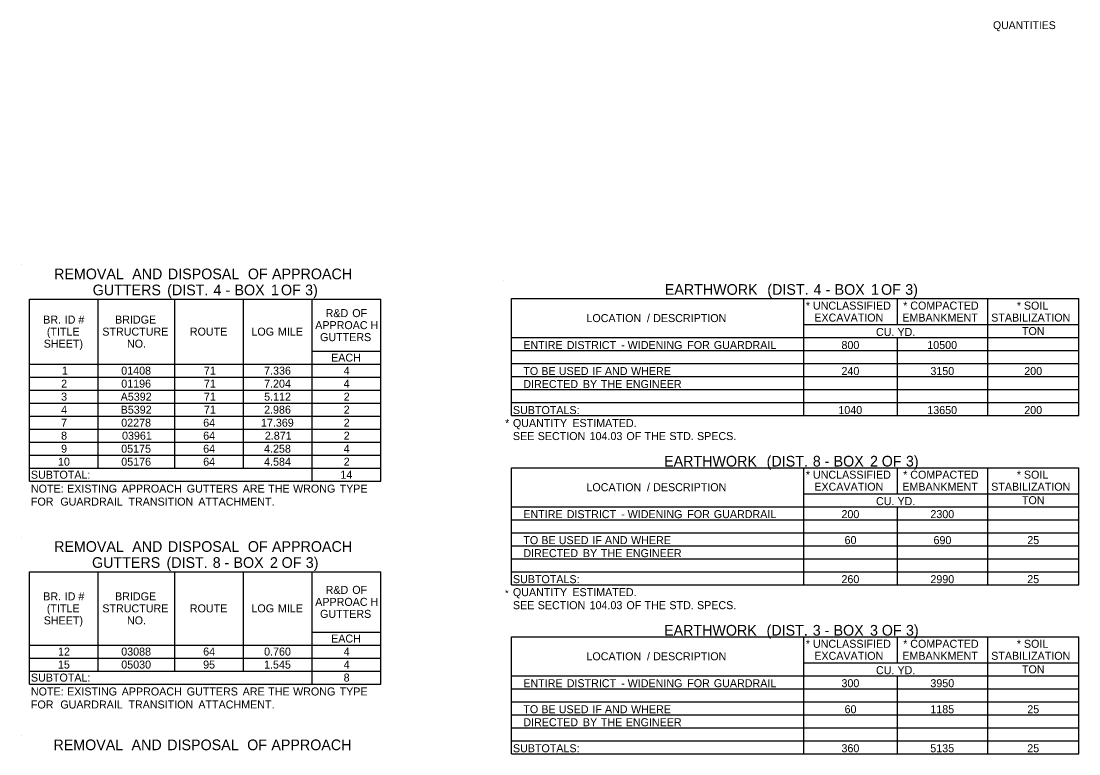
# Model space of a CAD drawing. Extents: x 540541 to 1930787, y -1948574 to 596640.
# Drawn here: x 544935 to 545728, y -1948135 to -1947586 of the extents above; entities that cross this region are included whole.
import ezdxf

# ---------------------------------------------------------------- set-up
doc = ezdxf.new("R2010")
doc.units = 0
for name, color, linetype in [('Default', 7, 'Continuous'), ('R_Border', 7, 'Continuous'), ('R_Border Prem', 7, 'Continuous')]:
    doc.layers.add(name, color=color, linetype=linetype)

msp = doc.modelspace()

# ---------------------------------------------------------------- linework, layer by layer
at = {"layer": 'Default'}
for p, q in [((544941.18, -1947794.32), (545204.43, -1947794.32)), ((544941.18, -1947930.82), (544941.18, -1947794.32)), ((544941.18, -1947930.82), (544941.18, -1947794.32)), ((544992.66, -1947921.07), (544992.66, -1947794.32)), ((545049.99, -1947921.07), (545049.99, -1947794.32)), ((545101.47, -1947921.07), (545101.47, -1947794.32)), ((545152.95, -1947930.82), (545152.95, -1947794.32)), ((545204.43, -1947930.82), (545204.43, -1947794.32)), ((545302.43, -1947793.93), (545727.53, -1947793.93)), ((545302.43, -1947871.93), (545302.43, -1947793.93)), ((545302.43, -1947881.68), (545302.43, -1947793.93)), ((545521.31, -1947881.68), (545521.31, -1947793.93)), ((545591.51, -1947813.43), (545591.51, -1947793.93)), ((545659.28, -1947881.68), (545659.28, -1947793.93)), ((545727.53, -1947881.68), (545727.53, -1947793.93)), ((545521.31, -1947813.43), (545727.53, -1947813.43)), ((545302.43, -1947823.18), (545727.53, -1947823.18)), ((545591.51, -1947881.68), (545591.51, -1947823.18)), ((545152.95, -1947833.32), (545204.43, -1947833.32)), ((545152.95, -1947833.32), (545204.43, -1947833.32)), ((545302.43, -1947832.93), (545727.53, -1947832.93)), ((544941.18, -1947843.07), (545204.43, -1947843.07)), ((545049.99, -1947921.07), (545049.99, -1947843.07)), ((545101.47, -1947921.07), (545101.47, -1947843.07)), ((545302.43, -1947842.68), (545727.53, -1947842.68)), ((544941.18, -1947852.82), (545204.43, -1947852.82)), ((545302.43, -1947852.43), (545727.53, -1947852.43)), ((544941.18, -1947862.57), (545204.43, -1947862.57)), ((544992.66, -1947921.07), (544992.66, -1947862.57)), ((545152.95, -1947930.82), (545152.95, -1947862.57)), ((545302.43, -1947862.18), (545727.53, -1947862.18)), ((544941.18, -1947872.32), (545204.43, -1947872.32)), ((545302.43, -1947871.93), (545727.53, -1947871.93)), ((544941.18, -1947882.07), (545204.43, -1947882.07)), ((545302.43, -1947881.68), (545727.53, -1947881.68)), ((544941.18, -1947891.82), (545204.43, -1947891.82)), ((544941.18, -1947901.57), (545204.43, -1947901.57)), ((544941.18, -1947911.32), (545204.43, -1947911.32)), ((544941.18, -1947921.07), (545204.43, -1947921.07)), ((544941.18, -1947921.07), (545204.43, -1947921.07)), ((545302.43, -1947920.68), (545727.53, -1947920.68)), ((545302.43, -1947998.68), (545302.43, -1947920.68)), ((545302.43, -1948008.43), (545302.43, -1947920.68)), ((545521.31, -1948008.43), (545521.31, -1947920.68)), ((545591.51, -1947940.18), (545591.51, -1947920.68)), ((545659.28, -1948008.43), (545659.28, -1947920.68)), ((545727.53, -1948008.43), (545727.53, -1947920.68)), ((544941.18, -1947930.82), (545204.43, -1947930.82)), ((545521.31, -1947940.18), (545727.53, -1947940.18)), ((545302.43, -1947949.93), (545727.53, -1947949.93)), ((545521.31, -1947949.93), (545659.28, -1947949.93)), ((545591.51, -1948008.43), (545591.51, -1947949.93)), ((545302.43, -1947959.68), (545727.53, -1947959.68)), ((545302.43, -1947969.43), (545727.53, -1947969.43)), ((545302.43, -1947979.18), (545727.53, -1947979.18)), ((545302.43, -1947988.93), (545727.53, -1947988.93)), ((544941.18, -1947998.64), (545204.43, -1947998.64)), ((544941.18, -1948082.88), (544941.18, -1947998.64)), ((544941.18, -1948082.88), (544941.18, -1947998.64)), ((544992.66, -1948073.13), (544992.66, -1947998.64)), ((545049.99, -1948073.13), (545049.99, -1947998.64)), ((545101.47, -1948073.13), (545101.47, -1947998.64)), ((545152.95, -1948082.88), (545152.95, -1947998.64)), ((545204.43, -1948082.88), (545204.43, -1947998.64)), ((545302.43, -1947998.68), (545727.53, -1947998.68)), ((545302.43, -1948008.43), (545727.53, -1948008.43)), ((545152.95, -1948043.88), (545204.43, -1948043.88)), ((545152.95, -1948043.88), (545204.43, -1948043.88)), ((544941.18, -1948053.63), (545204.43, -1948053.63)), ((544992.66, -1948073.13), (544992.66, -1948053.63)), ((545049.99, -1948073.13), (545049.99, -1948053.63)), ((545101.47, -1948073.13), (545101.47, -1948053.63)), ((545152.95, -1948082.88), (545152.95, -1948053.63)), ((545302.43, -1948047.43), (545727.53, -1948047.43)), ((545302.43, -1948125.43), (545302.43, -1948047.43)), ((545302.43, -1948135.18), (545302.43, -1948047.43)), ((545521.31, -1948135.18), (545521.31, -1948047.43)), ((545591.51, -1948066.93), (545591.51, -1948047.43)), ((545659.28, -1948135.18), (545659.28, -1948047.43)), ((545727.53, -1948135.18), (545727.53, -1948047.43)), ((544941.18, -1948063.38), (545204.43, -1948063.38)), ((545521.31, -1948066.93), (545727.53, -1948066.93)), ((544941.18, -1948073.13), (545204.43, -1948073.13)), ((544941.18, -1948073.13), (545204.43, -1948073.13)), ((545302.43, -1948076.68), (545727.53, -1948076.68)), ((545591.51, -1948135.18), (545591.51, -1948076.68)), ((544941.18, -1948082.88), (545204.43, -1948082.88)), ((545302.43, -1948086.43), (545727.53, -1948086.43)), ((545302.43, -1948096.18), (545727.53, -1948096.18)), ((545302.43, -1948105.93), (545727.53, -1948105.93)), ((545302.43, -1948115.68), (545727.53, -1948115.68)), ((545302.43, -1948125.43), (545727.53, -1948125.43)), ((545302.43, -1948135.18), (545727.53, -1948135.18))]:
    msp.add_line(p, q, dxfattribs=at)
at = {"layer": 'R_Border'}
for p, q in [((544935.33, -1947768.58), (544935.33, -1947768.58)), ((545296.58, -1947780.28), (545296.58, -1947780.28)), ((544935.33, -1947972.9), (544935.33, -1947972.9)), ((544934.85, -1948121.57), (544934.85, -1948121.57))]:
    msp.add_line(p, q, dxfattribs=at)

# ---------------------------------------------------------------- texts
at = {"layer": 'Default'}
for s, height, p in [('REMOVAL', 8, (544959.52, -1947779.45)), (' AND', 8, (545015.08, -1947779.45)), (' DISPOSAL', 8, (545041.85, -1947779.45)), (' OF', 8, (545101.77, -1947779.45)), (' APPROACH', 8, (545119.87, -1947779.45)), ('GUTTERS', 8, (544988.47, -1947791.45)), (' (DIST.', 8, (545041.33, -1947791.45)), (' 4', 8, (545075.95, -1947791.45)), (' BOX', 8, (545091.76, -1947791.45)), (' 1', 8, (545119.08, -1947791.45)), (' OF', 8, (545126.58, -1947791.45)), (' 3)', 8, (545144.69, -1947791.45)), ('EARTHWORK', 8, (545417.2, -1947791.1)), (' (DIST.', 8, (545491.08, -1947791.1)), (' 4', 8, (545525.7, -1947791.1)), (' BOX', 8, (545541.51, -1947791.1)), (' 1', 8, (545568.83, -1947791.1)), (' OF', 8, (545576.33, -1947791.1)), (' 3)', 8, (545594.44, -1947791.1)), (' -', 8, (545085.02, -1947791.45)), (' -', 8, (545534.77, -1947791.1)), ('*', 6, (545522.94, -1947802.18)), (' UNCLASSIFIED', 6, (545526.02, -1947802.18)), ('*', 6, (545595.88, -1947802.18)), (' COMPACTED', 6, (545598.96, -1947802.18)), ('*', 6, (545681.04, -1947802.18)), (' SOIL', 6, (545684.12, -1947802.18)), ('BR.', 6, (544951.4, -1947812.69)), (' ID', 6, (544965.26, -1947812.69)), (' #', 6, (544975.55, -1947812.69)), ('BRIDGE', 6, (545005.23, -1947812.69)), ('R&D', 6, (545163.03, -1947807.82)), (' OF', 6, (545180.78, -1947807.82)), ('LOCATION', 6, (545358.51, -1947811.55)), (' /', 6, (545401.62, -1947811.55)), (' DESCRIPTION', 6, (545406.28, -1947811.55)), ('EXCAVATION', 6, (545529.27, -1947811.18)), ('EMBANKMENT', 6, (545595.21, -1947811.18)), ('STABILIZATION', 6, (545661.84, -1947811.18)), ('(TITLE', 6, (544954.09, -1947821.69)), ('STRUCTURE', 6, (544995.68, -1947821.69)), ('ROUTE', 6, (545061.27, -1947821.69)), ('LOG', 6, (545107.42, -1947821.69)), (' MILE', 6, (545125.07, -1947821.69)), ('APPROAC', 6, (545155.24, -1947816.82)), ('H', 6, (545196.74, -1947816.82)), ('CU.', 6, (545575.5, -1947821.98)), (' YD.', 6, (545589.36, -1947821.98)), ('TON', 6, (545684.89, -1947821.3)), ('GUTTERS', 6, (545158.87, -1947825.82)), ('SHEET)', 6, (544951.77, -1947830.69)), ('NO.', 6, (545014.16, -1947830.69)), ('ENTIRE', 6, (545311.2, -1947831.73)), (' DISTRICT', 6, (545341.5, -1947831.73)), (' -', 6, (545382.31, -1947831.73)), (' WIDENING', 6, (545387.17, -1947831.73)), (' FOR', 6, (545431.82, -1947831.73)), (' GUARDRAIL', 6, (545451.73, -1947831.73)), ('800', 6, (545549.63, -1947831.73)), ('10500', 6, (545613.95, -1947831.73)), ('EACH', 6, (545167.14, -1947841.19)), ('1', 6, (544965.36, -1947850.94)), ('01408', 6, (545009.86, -1947850.94)), ('71', 6, (545071.84, -1947850.94)), ('7.336', 6, (545116.92, -1947850.94)), ('4', 6, (545176.57, -1947850.94)), ('TO', 6, (545311.2, -1947851.23)), (' BE', 6, (545322.47, -1947851.23)), (' USED', 6, (545335.54, -1947851.23)), (' IF', 6, (545360.71, -1947851.23)), (' AND', 6, (545370.1, -1947851.23)), (' WHERE', 6, (545389.69, -1947851.23)), ('240', 6, (545549.63, -1947851.23)), ('3150', 6, (545616.28, -1947851.23)), ('200', 6, (545686.61, -1947851.23)), ('2', 6, (544964.81, -1947860.69)), ('01196', 6, (545009.87, -1947860.69)), ('71', 6, (545071.84, -1947860.69)), ('7.204', 6, (545116.93, -1947860.69)), ('4', 6, (545176.57, -1947860.69)), ('DIRECTED', 6, (545311.2, -1947860.98)), (' BY', 6, (545353.61, -1947860.98)), (' THE', 6, (545367.06, -1947860.98)), (' ENGINEER', 6, (545385.71, -1947860.98)), ('3', 6, (544964.78, -1947870.44)), ('A5392', 6, (545009.43, -1947870.44)), ('71', 6, (545071.84, -1947870.44)), ('5.112', 6, (545116.95, -1947870.44)), ('2', 6, (545176.58, -1947870.44)), ('4', 6, (544964.8, -1947880.19)), ('B5392', 6, (545009.43, -1947880.19)), ('71', 6, (545071.84, -1947880.19)), ('2.986', 6, (545116.92, -1947880.19)), ('2', 6, (545176.58, -1947880.19)), ('SUBTOTALS:', 6, (545303.4, -1947880.48)), ('1040', 6, (545547.3, -1947880.48)), ('13650', 6, (545613.95, -1947880.48)), ('200', 6, (545686.62, -1947880.48)), ('7', 6, (544964.78, -1947889.94)), ('02278', 6, (545009.86, -1947889.94)), ('64', 6, (545071.28, -1947889.94)), ('17.369', 6, (545114.58, -1947889.94)), ('2', 6, (545176.58, -1947889.94)), ('*', 6, (545297.55, -1947890.23)), ('QUANTITY', 6, (545303.4, -1947890.23)), (' ESTIMATED.', 6, (545345.73, -1947890.23)), ('8', 6, (544964.78, -1947899.69)), ('03961', 6, (545010.45, -1947899.69)), ('64', 6, (545071.28, -1947899.69)), ('2.871', 6, (545117.5, -1947899.69)), ('2', 6, (545176.58, -1947899.69)), ('SEE', 6, (545303.4, -1947899.98)), (' SECTION', 6, (545319.73, -1947899.98)), (' 104.03', 6, (545358.64, -1947899.98)), (' OF', 6, (545386.22, -1947899.98)), (' THE', 6, (545399.8, -1947899.98)), (' STD.', 6, (545418.45, -1947899.98)), (' SPECS.', 6, (545439.15, -1947899.98)), ('9', 6, (544964.78, -1947909.44)), ('05175', 6, (545009.84, -1947909.44)), ('64', 6, (545071.28, -1947909.44)), ('4.258', 6, (545116.91, -1947909.44)), ('4', 6, (545176.57, -1947909.44)), (' (DIST.', 8, (545490.58, -1947919.8)), (' 3)', 8, (545594.94, -1947919.8)), ('10', 6, (544962.46, -1947919.19)), ('05176', 6, (545009.87, -1947919.19)), ('64', 6, (545071.28, -1947919.19)), ('4.584', 6, (545116.93, -1947919.19)), ('2', 6, (545176.58, -1947919.19)), ('EARTHWORK', 8, (545416.7, -1947919.8)), (' 8', 8, (545525.2, -1947919.8)), (' -', 8, (545534.02, -1947919.8)), (' BOX', 8, (545540.76, -1947919.8)), (' 2', 8, (545568.08, -1947919.8)), (' OF', 8, (545576.84, -1947919.8)), ('SUBTOTAL:', 6, (544942.16, -1947928.94)), ('14', 6, (545174.13, -1947928.94)), ('*', 6, (545522.94, -1947928.93)), (' UNCLASSIFIED', 6, (545526.02, -1947928.93)), ('*', 6, (545595.88, -1947928.93)), (' COMPACTED', 6, (545598.96, -1947928.93)), ('*', 6, (545681.04, -1947928.93)), (' SOIL', 6, (545684.12, -1947928.93)), ('NOTE:', 6, (544942.16, -1947939.37)), (' EXISTING', 6, (544967.04, -1947939.37)), (' APPROACH', 6, (545007.98, -1947939.37)), (' GUTTERS', 6, (545056.69, -1947939.37)), (' ARE', 6, (545098.64, -1947939.37)), (' THE', 6, (545117.76, -1947939.37)), (' WRONG', 6, (545136.41, -1947939.37)), (' TYPE', 6, (545171.27, -1947939.37)), ('LOCATION', 6, (545358.51, -1947938.3)), (' /', 6, (545401.62, -1947938.3)), (' DESCRIPTION', 6, (545406.28, -1947938.3)), ('EXCAVATION', 6, (545529.27, -1947937.93)), ('EMBANKMENT', 6, (545595.21, -1947937.93)), ('STABILIZATION', 6, (545661.84, -1947937.93)), ('FOR', 6, (544942.16, -1947949.12)), ('  GUARDRAIL', 6, (544959.74, -1947949.12)), (' TRANSITION', 6, (545013.01, -1947949.12)), (' ATTACHMENT.', 6, (545065.43, -1947949.12)), ('CU.', 6, (545575.5, -1947948.73)), (' YD.', 6, (545589.36, -1947948.73)), ('TON', 6, (545684.89, -1947948.05)), ('ENTIRE', 6, (545311.2, -1947958.48)), (' DISTRICT', 6, (545341.5, -1947958.48)), (' -', 6, (545382.31, -1947958.48)), (' WIDENING', 6, (545387.17, -1947958.48)), (' FOR', 6, (545431.82, -1947958.48)), (' GUARDRAIL', 6, (545451.73, -1947958.48)), ('200', 6, (545549.63, -1947958.48)), ('2300', 6, (545616.28, -1947958.48)), ('TO', 6, (545311.2, -1947977.98)), (' BE', 6, (545322.47, -1947977.98)), (' USED', 6, (545335.54, -1947977.98)), (' IF', 6, (545360.71, -1947977.98)), (' AND', 6, (545370.1, -1947977.98)), (' WHERE', 6, (545389.69, -1947977.98)), ('60', 6, (545551.96, -1947977.98)), ('690', 6, (545618.61, -1947977.98)), ('25', 6, (545688.91, -1947977.98)), ('REMOVAL', 8, (544959.52, -1947983.77)), (' AND', 8, (545015.08, -1947983.77)), (' DISPOSAL', 8, (545041.85, -1947983.77)), (' OF', 8, (545101.77, -1947983.77)), (' APPROACH', 8, (545119.87, -1947983.77)), ('DIRECTED', 6, (545311.2, -1947987.73)), (' BY', 6, (545353.61, -1947987.73)), (' THE', 6, (545367.06, -1947987.73)), (' ENGINEER', 6, (545385.71, -1947987.73)), ('GUTTERS', 8, (544987.96, -1947995.77)), (' (DIST.', 8, (545040.83, -1947995.77)), (' 8', 8, (545075.45, -1947995.77)), (' BOX', 8, (545091.01, -1947995.77)), (' 2', 8, (545118.33, -1947995.77)), (' OF', 8, (545127.09, -1947995.77)), (' 3)', 8, (545145.19, -1947995.77)), (' -', 8, (545084.27, -1947995.77)), ('SUBTOTALS:', 6, (545303.4, -1948007.23)), ('260', 6, (545549.63, -1948007.23)), ('2990', 6, (545616.28, -1948007.23)), ('25', 6, (545688.87, -1948007.23)), ('BR.', 6, (544951.4, -1948020.14)), (' ID', 6, (544965.26, -1948020.14)), (' #', 6, (544975.55, -1948020.14)), ('BRIDGE', 6, (545005.23, -1948020.14)), ('R&D', 6, (545163.03, -1948015.26)), (' OF', 6, (545180.78, -1948015.26)), ('*', 5, (545297.55, -1948017.18)), ('QUANTITY', 6, (545303.4, -1948016.98)), (' ESTIMATED.', 6, (545345.73, -1948016.98)), ('APPROAC', 6, (545155.24, -1948024.26)), ('H', 6, (545196.74, -1948024.26)), ('SEE', 6, (545303.4, -1948026.73)), (' SECTION', 6, (545319.73, -1948026.73)), (' 104.03', 6, (545358.64, -1948026.73)), (' OF', 6, (545386.22, -1948026.73)), (' THE', 6, (545399.8, -1948026.73)), (' STD.', 6, (545418.45, -1948026.73)), (' SPECS.', 6, (545439.15, -1948026.73)), ('(TITLE', 6, (544954.09, -1948029.14)), ('STRUCTURE', 6, (544995.68, -1948029.14)), ('ROUTE', 6, (545061.27, -1948029.14)), ('LOG', 6, (545107.42, -1948029.14)), (' MILE', 6, (545125.07, -1948029.14)), ('GUTTERS', 6, (545158.87, -1948033.26)), ('SHEET)', 6, (544951.77, -1948038.14)), ('NO.', 6, (545014.16, -1948038.14)), (' (DIST.', 8, (545490.53, -1948046.55)), (' 3)', 8, (545594.99, -1948046.55)), ('EACH', 6, (545167.14, -1948051.76)), ('EARTHWORK', 8, (545416.65, -1948046.55)), (' 3', 8, (545525.15, -1948046.55)), (' -', 8, (545533.99, -1948046.55)), (' BOX', 8, (545540.73, -1948046.55)), (' 3', 8, (545568.05, -1948046.55)), (' OF', 8, (545576.88, -1948046.55)), ('*', 6, (545522.94, -1948055.68)), (' UNCLASSIFIED', 6, (545526.02, -1948055.68)), ('*', 6, (545595.88, -1948055.68)), (' COMPACTED', 6, (545598.96, -1948055.68)), ('*', 6, (545681.04, -1948055.68)), (' SOIL', 6, (545684.12, -1948055.68)), ('12', 6, (544962.48, -1948061.51)), ('03088', 6, (545009.86, -1948061.51)), ('64', 6, (545071.28, -1948061.51)), ('0.760', 6, (545116.93, -1948061.51)), ('4', 6, (545176.57, -1948061.51)), ('LOCATION', 6, (545358.51, -1948065.05)), (' /', 6, (545401.62, -1948065.05)), (' DESCRIPTION', 6, (545406.28, -1948065.05)), ('EXCAVATION', 6, (545529.27, -1948064.68)), ('EMBANKMENT', 6, (545595.21, -1948064.68)), ('STABILIZATION', 6, (545661.84, -1948064.68)), ('15', 6, (544962.43, -1948071.26)), ('05030', 6, (545009.88, -1948071.26)), ('95', 6, (545071.24, -1948071.26)), ('1.545', 6, (545116.9, -1948071.26)), ('4', 6, (545176.57, -1948071.26)), ('CU.', 6, (545575.5, -1948075.48)), (' YD.', 6, (545589.36, -1948075.48)), ('TON', 6, (545684.89, -1948074.8)), ('SUBTOTAL:', 6, (544942.16, -1948081.01)), ('8', 6, (545176.55, -1948081.01)), ('NOTE:', 6, (544942.16, -1948091.43)), (' EXISTING', 6, (544967.04, -1948091.43)), (' APPROACH', 6, (545007.98, -1948091.43)), (' GUTTERS', 6, (545056.69, -1948091.43)), (' ARE', 6, (545098.64, -1948091.43)), (' THE', 6, (545117.76, -1948091.43)), (' WRONG', 6, (545136.41, -1948091.43)), (' TYPE', 6, (545171.27, -1948091.43)), ('ENTIRE', 6, (545311.2, -1948085.23)), (' DISTRICT', 6, (545341.5, -1948085.23)), (' -', 6, (545382.31, -1948085.23)), (' WIDENING', 6, (545387.17, -1948085.23)), (' FOR', 6, (545431.82, -1948085.23)), (' GUARDRAIL', 6, (545451.73, -1948085.23)), ('300', 6, (545549.63, -1948085.23)), ('3950', 6, (545616.28, -1948085.23)), ('FOR', 6, (544942.16, -1948101.18)), ('  GUARDRAIL', 6, (544959.74, -1948101.18)), (' TRANSITION', 6, (545013.01, -1948101.18)), (' ATTACHMENT.', 6, (545065.43, -1948101.18)), ('TO', 6, (545311.2, -1948104.73)), (' BE', 6, (545322.47, -1948104.73)), (' USED', 6, (545335.54, -1948104.73)), (' IF', 6, (545360.71, -1948104.73)), (' AND', 6, (545370.1, -1948104.73)), (' WHERE', 6, (545389.69, -1948104.73)), ('60', 6, (545551.96, -1948104.73)), ('1185', 6, (545616.24, -1948104.73)), ('25', 6, (545688.91, -1948104.73)), ('DIRECTED', 6, (545311.2, -1948114.48)), (' BY', 6, (545353.61, -1948114.48)), (' THE', 6, (545367.06, -1948114.48)), (' ENGINEER', 6, (545385.71, -1948114.48)), ('REMOVAL', 8, (544959.03, -1948132.44)), (' AND', 8, (545014.59, -1948132.44)), (' DISPOSAL', 8, (545041.36, -1948132.44)), (' OF', 8, (545101.28, -1948132.44)), (' APPROACH', 8, (545119.39, -1948132.44)), ('SUBTOTALS:', 6, (545303.4, -1948133.98)), ('360', 6, (545549.63, -1948133.98)), ('5135', 6, (545616.2, -1948133.98)), ('25', 6, (545688.87, -1948133.98))]:
    msp.add_text(s, height=height, dxfattribs=at).set_placement(p)
at = {"layer": 'R_Border Prem'}
msp.add_text('QUANTITIES', height=5.862, rotation=360, dxfattribs=at).set_placement((545663.18, -1947591.92))

doc.saveas('drawing.dxf')
